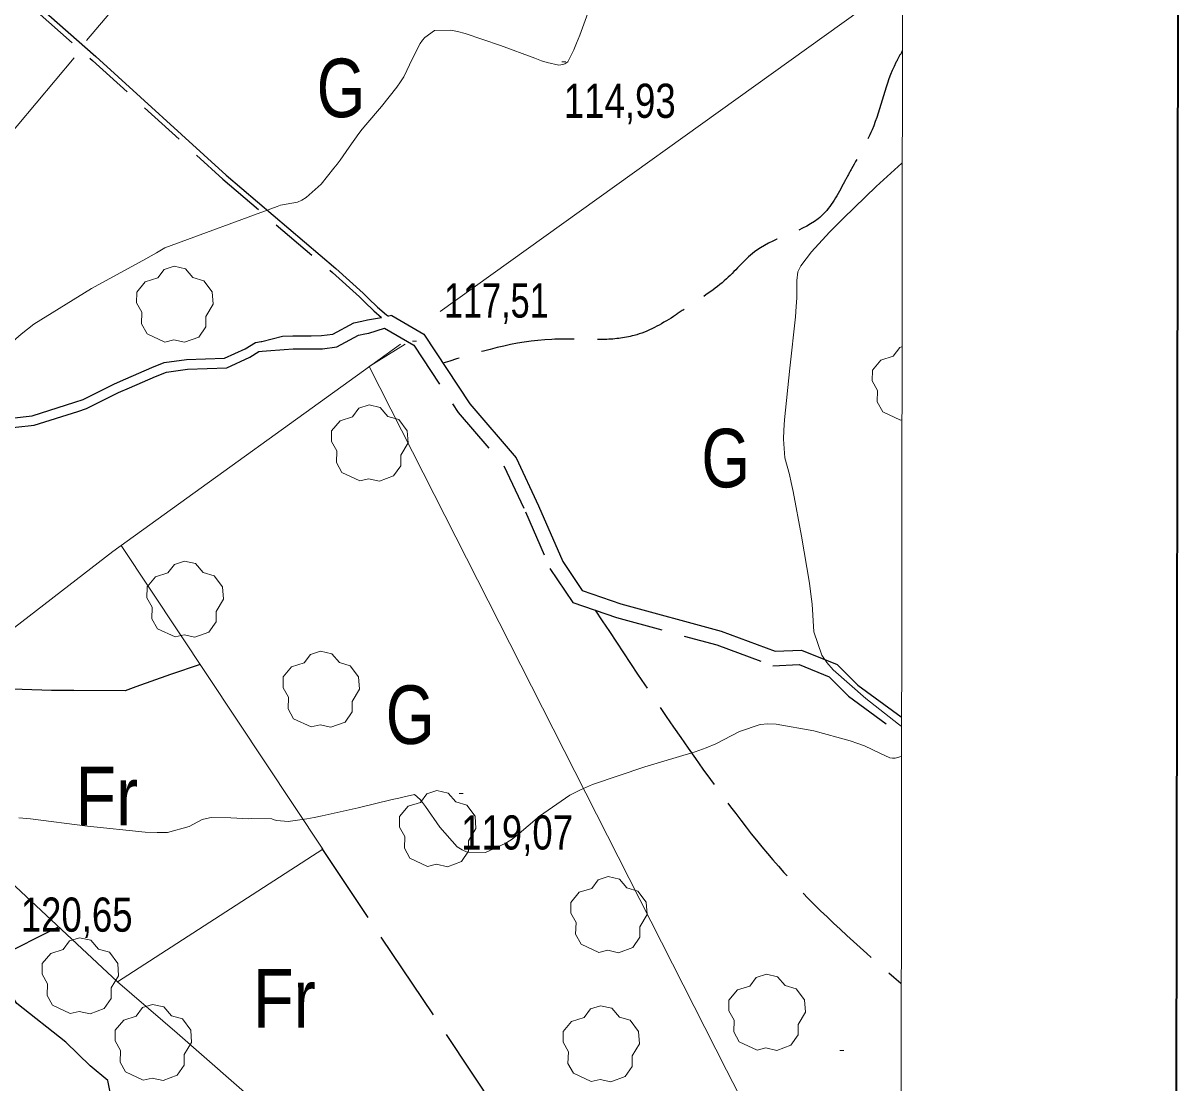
# Model space of a CAD drawing. Extents: x 487425 to 492029, y 4383576 to 4386788.
# Drawn here: x 491032.9 to 491328.9, y 4386033.6 to 4386304.9 of the extents above; entities that cross this region are included whole.
import ezdxf
from ezdxf.enums import TextEntityAlignment as Align

# ---------------------------------------------------------------- set-up
doc = ezdxf.new("R2010")
doc.units = 0
doc.header["$LTSCALE"] = 4
doc.linetypes.add('LONG_DASHED', pattern=[7.5, 6, -1.5])
doc.linetypes.add('MEDIUM_DASHED', pattern=[4.5, 3, -1.5])
for name, color, linetype, lineweight in [('1', 7, 'Continuous', 13), ('25', 7, 'LONG_DASHED', 25), ('29', 7, 'Continuous', 13), ('38', 7, 'Continuous', 25), ('51', 7, 'Continuous', 13), ('7', 7, 'Continuous', 13), ('9', 7, 'Continuous', 13)]:
    doc.layers.add(name, color=color, linetype=linetype, lineweight=lineweight)
doc.layers.add('31', color=7, linetype='Continuous')

msp = doc.modelspace()

# ---------------------------------------------------------------- linework, layer by layer
at = {"layer": '1', "lineweight": 35}
msp.add_lwpolyline([(487611.46, 4386512.7), (491328.86, 4386507.3), (491325.3, 4384052.3), (487607.9, 4384057.7)], close=True, dxfattribs=at)
at = {"layer": '1'}
msp.add_lwpolyline([(487681.9, 4386441.2), (491258.2, 4386436), (491255.4, 4384123.8), (487678, 4384129)], close=True, dxfattribs=at)
at = {"layer": '25'}
msp.add_line((491154.62, 4386026.01), (491109.5, 4386093.54), dxfattribs=at)
for points in [[(491078.2, 4386140.67), (491070.6, 4386138.11), (491061.74, 4386134.92), (491059.04, 4386133.95), (491045.84, 4386133.99), (491040.14, 4386134.01), (491027.62, 4386134.42), (491023.43, 4386135.78), (491015.86, 4386138.77)], [(490912.89, 4386064.39), (490940.71, 4386056.93), (490963.85, 4386048.24), (490969.92, 4386045.74), (490987.51, 4386036.99), (490997.32, 4386031.94), (491011.55, 4386025.9), (491020.31, 4386023.02), (491051.96, 4386024.43), (491055.79, 4386028.16), (491054.61, 4386034.16), (491050.05, 4386037.93), (491043.84, 4386044.02), (491031.28, 4386053.88), (491027.25, 4386060.27), (491025.16, 4386065.07), (491041.97, 4386073.53)]]:
    msp.add_lwpolyline(points, dxfattribs=at)
at = {"layer": '29'}
for p, q in [((491257.84, 4386221.97), (491257.94, 4386222)), ((491257.82, 4386203.29), (491257.56, 4386203.23)), ((491257.92, 4386203.31), (491257.82, 4386203.29))]:
    msp.add_line(p, q, dxfattribs=at)
for points in [[(491069.18, 4386223.24), (491064.64, 4386225.36), (491063.23, 4386227.9), (491063.33, 4386230.88), (491061.96, 4386233.29), (491062, 4386236.04), (491064.16, 4386238.64), (491067.35, 4386239.64), (491069, 4386241.83), (491071.57, 4386242.66), (491074.43, 4386242.01), (491076.38, 4386239.74), (491079.19, 4386238.92), (491081.32, 4386236.07), (491081.56, 4386232.94), (491079.68, 4386229.79), (491079.68, 4386227.11), (491077.86, 4386224.5), (491074.24, 4386223.16), (491071.47, 4386223.79)], [(491119.08, 4386187.7), (491114.54, 4386189.82), (491113.13, 4386192.36), (491113.23, 4386195.34), (491111.86, 4386197.75), (491111.9, 4386200.5), (491114.06, 4386203.1), (491117.25, 4386204.1), (491118.9, 4386206.29), (491121.47, 4386207.12), (491124.33, 4386206.47), (491126.28, 4386204.2), (491129.09, 4386203.38), (491131.22, 4386200.53), (491131.46, 4386197.4), (491129.58, 4386194.25), (491129.58, 4386191.57), (491127.76, 4386188.96), (491124.14, 4386187.62), (491121.37, 4386188.25)], [(491071.8, 4386147.73), (491067.26, 4386149.85), (491065.85, 4386152.39), (491065.95, 4386155.37), (491064.58, 4386157.78), (491064.62, 4386160.53), (491066.78, 4386163.13), (491069.97, 4386164.13), (491071.62, 4386166.32), (491074.19, 4386167.15), (491077.05, 4386166.5), (491079, 4386164.23), (491081.81, 4386163.41), (491083.94, 4386160.56), (491084.18, 4386157.43), (491082.3, 4386154.28), (491082.3, 4386151.6), (491080.48, 4386148.99), (491076.86, 4386147.65), (491074.09, 4386148.28)], [(491106.67, 4386124.68), (491102.13, 4386126.8), (491100.72, 4386129.34), (491100.82, 4386132.32), (491099.45, 4386134.73), (491099.49, 4386137.48), (491101.65, 4386140.08), (491104.84, 4386141.08), (491106.49, 4386143.27), (491109.06, 4386144.1), (491111.92, 4386143.45), (491113.87, 4386141.18), (491116.68, 4386140.36), (491118.81, 4386137.51), (491119.05, 4386134.38), (491117.17, 4386131.23), (491117.17, 4386128.55), (491115.35, 4386125.94), (491111.73, 4386124.6), (491108.96, 4386125.23)], [(491136.48, 4386088.98), (491131.94, 4386091.1), (491130.53, 4386093.64), (491130.63, 4386096.62), (491129.26, 4386099.03), (491129.3, 4386101.78), (491131.46, 4386104.38), (491134.65, 4386105.38), (491136.3, 4386107.57), (491138.87, 4386108.4), (491141.73, 4386107.75), (491143.68, 4386105.48), (491146.49, 4386104.66), (491148.62, 4386101.81), (491148.86, 4386098.68), (491146.98, 4386095.53), (491146.98, 4386092.85), (491145.16, 4386090.24), (491141.54, 4386088.9), (491138.77, 4386089.53)], [(491180.33, 4386066.97), (491175.79, 4386069.09), (491174.38, 4386071.63), (491174.48, 4386074.61), (491173.11, 4386077.02), (491173.15, 4386079.77), (491175.31, 4386082.37), (491178.5, 4386083.37), (491180.15, 4386085.56), (491182.72, 4386086.39), (491185.58, 4386085.74), (491187.53, 4386083.47), (491190.34, 4386082.65), (491192.47, 4386079.8), (491192.71, 4386076.67), (491190.83, 4386073.52), (491190.83, 4386070.84), (491189.01, 4386068.23), (491185.39, 4386066.89), (491182.62, 4386067.52)], [(491044.97, 4386051.31), (491040.43, 4386053.43), (491039.02, 4386055.97), (491039.12, 4386058.95), (491037.75, 4386061.36), (491037.79, 4386064.11), (491039.95, 4386066.71), (491043.14, 4386067.71), (491044.79, 4386069.9), (491047.36, 4386070.73), (491050.22, 4386070.08), (491052.17, 4386067.81), (491054.98, 4386066.99), (491057.11, 4386064.14), (491057.35, 4386061.01), (491055.47, 4386057.86), (491055.47, 4386055.18), (491053.65, 4386052.57), (491050.03, 4386051.23), (491047.26, 4386051.86)], [(491220.83, 4386041.96), (491216.29, 4386044.08), (491214.88, 4386046.62), (491214.98, 4386049.6), (491213.61, 4386052.01), (491213.65, 4386054.76), (491215.81, 4386057.36), (491219, 4386058.36), (491220.65, 4386060.55), (491223.22, 4386061.38), (491226.08, 4386060.73), (491228.03, 4386058.46), (491230.84, 4386057.64), (491232.97, 4386054.79), (491233.21, 4386051.66), (491231.33, 4386048.51), (491231.33, 4386045.83), (491229.51, 4386043.22), (491225.89, 4386041.88), (491223.12, 4386042.51)], [(491063.66, 4386034.24), (491059.12, 4386036.36), (491057.71, 4386038.9), (491057.81, 4386041.88), (491056.44, 4386044.29), (491056.48, 4386047.04), (491058.64, 4386049.64), (491061.83, 4386050.64), (491063.48, 4386052.83), (491066.05, 4386053.66), (491068.91, 4386053.01), (491070.86, 4386050.74), (491073.67, 4386049.92), (491075.8, 4386047.07), (491076.04, 4386043.94), (491074.16, 4386040.79), (491074.16, 4386038.11), (491072.34, 4386035.5), (491068.72, 4386034.16), (491065.95, 4386034.79)], [(491178.37, 4386033.9), (491173.83, 4386036.02), (491172.42, 4386038.56), (491172.52, 4386041.54), (491171.15, 4386043.95), (491171.19, 4386046.7), (491173.35, 4386049.3), (491176.54, 4386050.3), (491178.19, 4386052.49), (491180.76, 4386053.32), (491183.62, 4386052.67), (491185.57, 4386050.4), (491188.38, 4386049.58), (491190.51, 4386046.73), (491190.75, 4386043.6), (491188.87, 4386040.45), (491188.87, 4386037.77), (491187.05, 4386035.16), (491183.43, 4386033.82), (491180.66, 4386034.45)]]:
    msp.add_lwpolyline(points, close=True, dxfattribs=at)
msp.add_lwpolyline([(491257.56, 4386203.23), (491253.02, 4386205.35), (491251.61, 4386207.89), (491251.71, 4386210.87), (491250.34, 4386213.28), (491250.38, 4386216.03), (491252.54, 4386218.63), (491255.73, 4386219.63), (491257.38, 4386221.82), (491257.84, 4386221.97)], dxfattribs=at)
at = {"layer": '38', "linetype": 'LONG_DASHED'}
for p, q in [((491258.03, 4386297.75), (491257.93, 4386297.57)), ((491257.65, 4386059.1), (491257.74, 4386059.01))]:
    msp.add_line(p, q, dxfattribs=at)
at = {"layer": '38'}
for p, q in [((491127.28, 4386230.02), (491126.42, 4386229.84)), ((491257.73, 4386127.28), (491257.83, 4386127.21))]:
    msp.add_line(p, q, dxfattribs=at)
at = {"layer": '38', "linetype": 'MEDIUM_DASHED'}
msp.add_line((491257.73, 4386122.7), (491257.82, 4386122.63), dxfattribs=at)
for points in [[(491036.45, 4386307.75), (491050.64, 4386295.35), (491083.99, 4386264.95), (491112.11, 4386241.02), (491119.04, 4386234.81), (491120.29, 4386233.55), (491122.72, 4386231.19), (491124.67, 4386229.54)], [(491095.23, 4386221), (491099.78, 4386221.35), (491102.04, 4386221.47), (491104.36, 4386221.47), (491106.65, 4386221.46), (491109.58, 4386221.53), (491113.22, 4386221.97), (491118.74, 4386224.96), (491120.36, 4386225.32), (491121.44, 4386225.53), (491125.44, 4386226.78)], [(491125.44, 4386226.78), (491132.92, 4386222.47), (491144.29, 4386205.19), (491156.01, 4386191.57), (491161.52, 4386179.76), (491167.81, 4386165.23), (491173.69, 4386156.58), (491184.83, 4386152.67), (491210.51, 4386145.7), (491224.9, 4386140.37), (491231.59, 4386140.64), (491239.31, 4386137.53), (491244.22, 4386132.59), (491257.73, 4386122.7)], [(491024, 4386200.64), (491035.73, 4386201.92), (491046.86, 4386205.49), (491049.16, 4386206.22), (491057.31, 4386210.31), (491060.17, 4386211.54), (491066.82, 4386214.43), (491069.64, 4386215.56), (491074.97, 4386216.31), (491085.02, 4386216.66), (491090.91, 4386219.34), (491093.22, 4386220.78), (491094.09, 4386220.91), (491095.23, 4386221)]]:
    msp.add_lwpolyline(points, dxfattribs=at)
at = {"layer": '38'}
for points in [[(491037.32, 4386308.77), (491051.52, 4386296.35), (491084.87, 4386265.96), (491112.99, 4386242.03), (491119.96, 4386235.78), (491121.23, 4386234.5), (491123.62, 4386232.17), (491125.93, 4386230.22), (491126.42, 4386229.84)], [(491094, 4386223.38), (491099.29, 4386224.7), (491101.95, 4386224.84), (491104.37, 4386224.84), (491106.61, 4386224.83), (491109.34, 4386224.9), (491112.2, 4386225.23), (491117.56, 4386228.11), (491119.63, 4386228.6), (491121.09, 4386228.91), (491124.67, 4386229.54)], [(491127.28, 4386229.99), (491135.53, 4386225.24), (491147.25, 4386207.42), (491159.14, 4386193.59), (491164.89, 4386181.28), (491171.07, 4386167.02), (491176.07, 4386159.66), (491185.93, 4386156.2), (491211.64, 4386149.23), (491225.49, 4386144.09), (491232.24, 4386144.37), (491241.39, 4386140.67), (491246.64, 4386135.4), (491257.73, 4386127.28)], [(491023.79, 4386203.1), (491035.21, 4386204.34), (491046.11, 4386207.84), (491048.23, 4386208.51), (491056.27, 4386212.55), (491059.19, 4386213.81), (491065.87, 4386216.71), (491069, 4386217.97), (491074.75, 4386218.77), (491084.45, 4386219.11), (491089.74, 4386221.52), (491092.36, 4386223.15), (491093.82, 4386223.36), (491094, 4386223.38)]]:
    msp.add_lwpolyline(points, dxfattribs=at)
at = {"layer": '38', "linetype": 'LONG_DASHED'}
for points in [[(491257.93, 4386297.57), (491256.41, 4386294.84), (491250.29, 4386277.54), (491245.02, 4386267.58), (491243.21, 4386264.21), (491237.33, 4386255.53), (491220.74, 4386246.72), (491212.99, 4386239.39), (491203.45, 4386232.45), (491199.4, 4386229.76), (491189.34, 4386224.91), (491181.38, 4386223.88), (491168.26, 4386223.92), (491140.41, 4386217.83)], [(491179.4, 4386154.59), (491208.9, 4386111.25), (491230.65, 4386084.2), (491257.65, 4386059.1)]]:
    msp.add_spline(points, degree=3, dxfattribs=at)
at = {"layer": '51'}
for p, q in [((491139.71, 4386231.04), (491257.95, 4386315.89)), ((490965.96, 4386200.89), (491045.96, 4386296.02)), ((491057.09, 4386059.43), (491072.35, 4386046.29))]:
    msp.add_line(p, q, dxfattribs=at)
for points in [[(491049.12, 4386300.43), (491108.34, 4386370.29), (491097.45, 4386388.24)], [(491129.49, 4386222.66), (491055.85, 4386169.57), (490992.26, 4386120.58), (490910.74, 4386062.87)], [(491130.69, 4386222.67), (491121.53, 4386217), (491213.05, 4386036.78), (491257.52, 4385950.27)], [(491057.98, 4386171.11), (491109.6, 4386093.38), (491057.09, 4386059.43), (490991.8, 4386120.25)], [(491072.35, 4386046.29), (491102.03, 4386020.3), (491108.39, 4386015.78), (491115.57, 4386010.65)]]:
    msp.add_lwpolyline(points, dxfattribs=at)
at = {"layer": '7'}
for p, q in [((491170.88, 4386295), (491171.88, 4386295)), ((491132.59, 4386223.48), (491133.59, 4386223.48)), ((491144.58, 4386107.68), (491145.58, 4386107.68)), ((491242.03, 4386041.88), (491243.03, 4386041.88))]:
    msp.add_line(p, q, dxfattribs=at)
at = {"layer": '9'}
for p, q in [((491257.9, 4386269.04), (491258, 4386269.13)), ((491257.82, 4386124.83), (491257.73, 4386124.91)), ((491257.72, 4386117.11), (491257.81, 4386117.14))]:
    msp.add_line(p, q, dxfattribs=at)
for points in [[(491097.92, 4386257.91), (491098.8, 4386258.3), (491103.12, 4386259.05), (491104.26, 4386259.56), (491105.37, 4386260.21), (491109.18, 4386263.66), (491112.49, 4386267.74), (491113.29, 4386268.78), (491114.05, 4386269.79), (491116.35, 4386273.13), (491118.83, 4386276.61), (491119.69, 4386277.71), (491120.63, 4386278.87), (491124.64, 4386283.54), (491128.61, 4386288.49), (491129.52, 4386289.83), (491130.35, 4386291.15), (491132.64, 4386295.8), (491134.56, 4386299.67), (491135.16, 4386300.5), (491135.78, 4386301.23), (491138.24, 4386302.98), (491142.44, 4386303.05), (491144.16, 4386302.71), (491146.11, 4386302.21), (491155.15, 4386299.14), (491163.89, 4386295.88), (491165.65, 4386295.26), (491167.13, 4386294.78), (491170.08, 4386294.08), (491171.1, 4386294.3), (491171.36, 4386294.39), (491171.61, 4386294.5), (491172.42, 4386295), (491173.93, 4386298.04), (491174.61, 4386299.75), (491175.42, 4386301.83), (491179.28, 4386312.48)], [(491229.16, 4386189.29), (491227.95, 4386193.62), (491227.6, 4386198.38), (491227.7, 4386200.66), (491227.88, 4386203.36), (491229.24, 4386216.55), (491230.66, 4386229.67), (491230.89, 4386232.32), (491231.05, 4386234.55), (491231, 4386239.02), (491231.27, 4386241.18), (491231.61, 4386241.93), (491232.08, 4386242.76), (491234.76, 4386246.32), (491239.41, 4386251.33), (491241.11, 4386253.06), (491243, 4386254.95), (491251.35, 4386263.02), (491257.9, 4386269.04)], [(490838, 4386169.61), (490882.07, 4386174.6), (490890.83, 4386176.89), (490900.42, 4386177.41), (490902.85, 4386177.38), (490905.18, 4386177.28), (490912.78, 4386176.27), (490925.65, 4386177.21), (490931.31, 4386178.32), (490937.88, 4386179.81), (490969.15, 4386188.28), (490999.95, 4386198.8), (491006.23, 4386201.59), (491011.52, 4386204.32), (491022.49, 4386213.71), (491029.56, 4386222.77), (491032.39, 4386225.29), (491035.61, 4386227.81), (491050.39, 4386236.96), (491064.34, 4386244.52), (491067.02, 4386246.04), (491069.2, 4386247.32), (491097.92, 4386257.91)], [(491257.73, 4386124.91), (491257.09, 4386125.44), (491248.71, 4386131.96), (491240.33, 4386139.34), (491238.73, 4386141.22), (491237.44, 4386143.04), (491235.41, 4386149.02), (491234.94, 4386156.14), (491234.63, 4386158.68), (491234.25, 4386161.46), (491232.26, 4386173.54), (491230.09, 4386184.93), (491229.6, 4386187.29), (491229.16, 4386189.29)], [(491031.79, 4386101.45), (491034.75, 4386101.14), (491049.4, 4386099.25), (491064.18, 4386097.72), (491067.23, 4386097.63), (491069.83, 4386097.7), (491075.45, 4386099.17), (491078.71, 4386101), (491079.81, 4386101.28), (491081.01, 4386101.48), (491086.07, 4386101.39), (491090.63, 4386101.16), (491091.5, 4386101.27), (491096.56, 4386101.15), (491097.15, 4386100.89), (491097.82, 4386100.7), (491100.77, 4386100.5), (491105.57, 4386101.17), (491107.41, 4386101.52), (491109.46, 4386101.93), (491118.69, 4386104.02), (491127.38, 4386106.08), (491129.1, 4386106.48), (491130.51, 4386106.81), (491133.13, 4386107.36), (491134.53, 4386106.12), (491135.17, 4386105.32), (491135.93, 4386104.32), (491139.59, 4386099.03), (491144.07, 4386094.03), (491145.33, 4386093.21), (491146.61, 4386092.63), (491151.33, 4386092.55), (491156.36, 4386094.89), (491157.84, 4386095.83), (491159.35, 4386096.9), (491165.1, 4386101.81), (491172.88, 4386107.24), (491175.66, 4386108.63), (491178.72, 4386109.98), (491192.06, 4386114.44), (491204.99, 4386118.36), (491207.79, 4386119.36), (491210.26, 4386120.33), (491216.35, 4386123.52), (491221.63, 4386125.34), (491223.58, 4386125.45), (491225.75, 4386125.38), (491235.37, 4386123.7), (491244.68, 4386121.1), (491246.66, 4386120.46), (491248.38, 4386119.85), (491252.43, 4386117.92), (491254.82, 4386116.79), (491255.49, 4386116.69), (491256.17, 4386116.67), (491257.72, 4386117.11)]]:
    msp.add_lwpolyline(points, dxfattribs=at)

# ---------------------------------------------------------------- texts
at = {"layer": '31'}
for s, width, p in [('G', 0.8, (491114.31, 4386280.79)), ('G', 0.8, (491212.82, 4386186.03)), ('G', 0.8, (491132, 4386120.33)), ('Fr', 0.85, (491054.33, 4386099.5)), ('Fr', 0.85, (491099.79, 4386047.69))]:
    msp.add_text(s, height=15, dxfattribs=dict(at, width=width)).set_placement(p, align=Align.CENTER)
at = {"layer": '7'}
for s, width, p in [('114,93', 0.8, (491171.38, 4386280.63)), ('117,51', 0.75, (491140.64, 4386229.49)), ('119,07', 0.8, (491145.08, 4386093.31)), ('120,65', 0.8, (491032.28, 4386072.27))]:
    msp.add_text(s, height=8.75, dxfattribs=dict(at, width=width)).set_placement(p)

doc.saveas('drawing.dxf')
